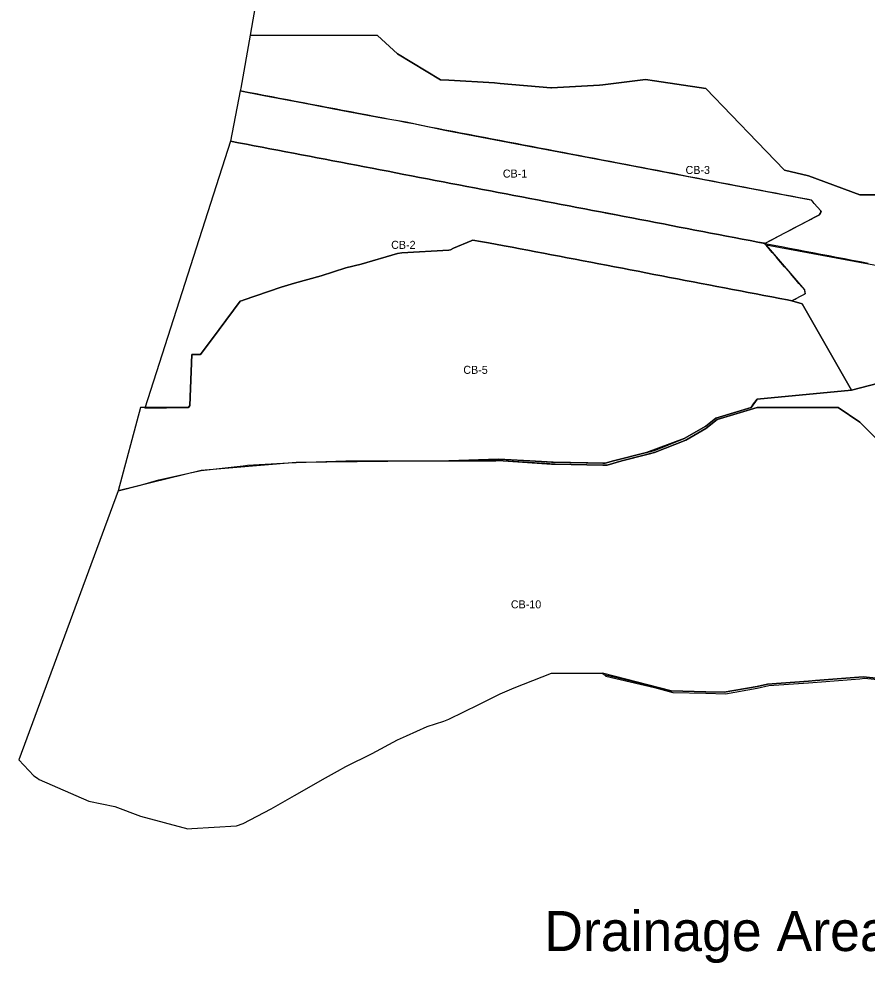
# Model space of a CAD drawing. Extents: x 2451 to 3960, y 2751 to 3762.
# Drawn here: x 2451 to 2980, y 2751 to 3341 of the extents above; entities that cross this region are included whole.
import ezdxf

# ---------------------------------------------------------------- set-up
doc = ezdxf.new("R2010")
doc.units = 0
doc.layers.add('SURVEY - DRAINAGE - Area Shapes', color=7, linetype='Continuous')
doc.layers.add('SURVEY - DRAINAGE - Area Shapes Text', color=7, linetype='Continuous')

msp = doc.modelspace()

# ---------------------------------------------------------------- linework, layer by layer
at = {"layer": 'SURVEY - DRAINAGE - Area Shapes'}
msp.add_line((2941.5, 3169.47), (2941.5, 3169.48), dxfattribs=at)
for points in [[(2670.29, 3761.98), (2595.31, 3330.82), (2674.6, 3330.56), (2687.08, 3319.1), (2713.92, 3302.79), (2719.15, 3302.62), (2747.77, 3300.95), (2751.23, 3300.64), (2782.84, 3297.86), (2783.31, 3297.89), (2813.27, 3299.56), (2815.38, 3299.78), (2842, 3303.03), (2847.46, 3302.35), (2879.54, 3297.37), (2911.62, 3264.19), (2928.65, 3246.56), (2943.69, 3242.98), (2975.77, 3231), (3007.85, 3231)], [(3007.85, 3231), (2975.77, 3231), (2943.69, 3242.98), (2928.65, 3246.56), (2911.62, 3264.19), (2879.54, 3297.37), (2847.46, 3302.35), (2842, 3303.03), (2815.38, 3299.78), (2813.27, 3299.56), (2783.31, 3297.89), (2782.84, 3297.86), (2751.23, 3300.64), (2747.77, 3300.95), (2719.15, 3302.62), (2713.92, 3302.79), (2687.08, 3319.1), (2674.6, 3330.56), (2655, 3330.56), (2622.92, 3330.56), (2595.31, 3330.82), (2589.39, 3297.7), (2589.06, 3295.97), (2603.8, 3293.15), (2628.35, 3288.46), (2652.91, 3283.76), (2677.46, 3279.06), (2692.62, 3276.59), (2716.75, 3271.54), (2765.86, 3262.14), (2829.7, 3249.93), (2893.54, 3237.71), (2945.12, 3227.91), (2951.27, 3221.06), (2951.47, 3220.52), (2950.51, 3218.66), (2916.37, 3200.75), (2926.81, 3198.76), (2931.72, 3197.82), (2936.63, 3196.88), (2941.54, 3195.94), (2946.46, 3195), (2951.37, 3194.06), (2956.28, 3193.12), (2961.19, 3192.18), (2966.1, 3191.24), (2971.01, 3190.3), (2975.92, 3189.36), (2980.83, 3188.42)], [(2946.56, 3226.54), (2946.33, 3226.81), (2945.51, 3227.76), (2945.52, 3227.81), (2942.65, 3228.31), (2937.74, 3229.25), (2932.83, 3230.19), (2927.92, 3231.13), (2923, 3232.07), (2918.09, 3233.01), (2913.18, 3233.95), (2908.27, 3234.89), (2903.36, 3235.83), (2898.45, 3236.77), (2893.54, 3237.71), (2888.63, 3238.65), (2883.72, 3239.59), (2878.81, 3240.53), (2873.9, 3241.47), (2868.99, 3242.41), (2864.07, 3243.35), (2859.16, 3244.29), (2854.25, 3245.23), (2849.34, 3246.17), (2844.43, 3247.11), (2839.52, 3248.05), (2834.61, 3248.99), (2829.7, 3249.93), (2824.79, 3250.86), (2819.88, 3251.8), (2814.97, 3252.74), (2810.05, 3253.68), (2805.14, 3254.62), (2800.23, 3255.56), (2795.32, 3256.5), (2790.41, 3257.44), (2785.5, 3258.38), (2780.59, 3259.32), (2775.68, 3260.26), (2770.77, 3261.2), (2765.86, 3262.14), (2760.95, 3263.08), (2756.03, 3264.02), (2751.12, 3264.96), (2746.21, 3265.9), (2741.3, 3266.84), (2736.39, 3267.78), (2731.48, 3268.72), (2726.57, 3269.66), (2721.66, 3270.6), (2716.75, 3271.54), (2711.84, 3272.48), (2706.93, 3273.42), (2702.01, 3274.36), (2697.1, 3275.3), (2692.19, 3276.24), (2687.28, 3277.18), (2682.37, 3278.12), (2677.46, 3279.06), (2672.55, 3280), (2667.64, 3280.94), (2662.73, 3281.88), (2657.82, 3282.82), (2652.91, 3283.76), (2648, 3284.7), (2643.08, 3285.64), (2638.17, 3286.58), (2633.26, 3287.52), (2628.35, 3288.46), (2623.44, 3289.4), (2618.53, 3290.33), (2613.62, 3291.27), (2608.71, 3292.21), (2603.8, 3293.15), (2598.89, 3294.09), (2593.98, 3295.03), (2589.06, 3295.97), (2583.05, 3264.54), (2587.96, 3263.6), (2592.87, 3262.66), (2597.78, 3261.72), (2602.69, 3260.79), (2607.6, 3259.84), (2612.52, 3258.91), (2617.43, 3257.97), (2622.34, 3257.03), (2627.25, 3256.09), (2632.16, 3255.15), (2637.07, 3254.21), (2641.98, 3253.27), (2646.89, 3252.33), (2651.8, 3251.39), (2656.71, 3250.45), (2661.62, 3249.51), (2666.54, 3248.57), (2671.45, 3247.63), (2676.36, 3246.69), (2681.27, 3245.75), (2686.18, 3244.81), (2691.09, 3243.87), (2696, 3242.93), (2700.91, 3241.99), (2705.82, 3241.05), (2710.73, 3240.11), (2715.64, 3239.17), (2720.55, 3238.23), (2725.47, 3237.29), (2730.38, 3236.35), (2735.29, 3235.41), (2740.2, 3234.47), (2745.11, 3233.53), (2750.02, 3232.59), (2754.93, 3231.65), (2759.84, 3230.71), (2764.75, 3229.77), (2769.66, 3228.83), (2774.57, 3227.89), (2779.49, 3226.95), (2784.4, 3226.01), (2789.31, 3225.07), (2794.22, 3224.13), (2799.13, 3223.19), (2804.04, 3222.25), (2808.95, 3221.32), (2813.86, 3220.37), (2818.77, 3219.44), (2823.68, 3218.5), (2828.59, 3217.56), (2833.51, 3216.62), (2838.42, 3215.68), (2843.33, 3214.74), (2848.24, 3213.8), (2853.15, 3212.86)], [(2941.5, 3169.48), (2941.5, 3169.51), (2941.29, 3171.55), (2937.68, 3175.76), (2935.89, 3177.84), (2933.52, 3180.6), (2932.33, 3181.99), (2929.36, 3185.45), (2928.73, 3186.18), (2925.19, 3190.3), (2923.44, 3192.34), (2921.03, 3195.14), (2917.21, 3199.58), (2916.87, 3199.99), (2916.69, 3200.19), (2916.17, 3200.8), (2912.08, 3201.58), (2907.17, 3202.52), (2902.26, 3203.46), (2897.35, 3204.4), (2892.44, 3205.34), (2887.53, 3206.28), (2882.61, 3207.22), (2877.7, 3208.16), (2872.79, 3209.1), (2867.88, 3210.04), (2862.97, 3210.98), (2858.06, 3211.92), (2853.15, 3212.86), (2848.24, 3213.8), (2843.33, 3214.74), (2838.42, 3215.68), (2833.51, 3216.62), (2828.59, 3217.56), (2823.68, 3218.5), (2813.86, 3220.37), (2808.95, 3221.32), (2804.04, 3222.25), (2799.13, 3223.19), (2794.22, 3224.13), (2789.31, 3225.07), (2784.4, 3226.01), (2779.49, 3226.95), (2774.57, 3227.89), (2769.66, 3228.83), (2764.75, 3229.77), (2759.84, 3230.71), (2754.93, 3231.65), (2750.02, 3232.59), (2745.11, 3233.53), (2740.2, 3234.47), (2735.29, 3235.41), (2730.38, 3236.35), (2725.47, 3237.29), (2720.55, 3238.23), (2715.64, 3239.17), (2710.73, 3240.11), (2705.82, 3241.05), (2700.91, 3241.99), (2696, 3242.93), (2691.09, 3243.87), (2686.18, 3244.81), (2681.27, 3245.75), (2676.36, 3246.69), (2671.45, 3247.63), (2666.54, 3248.57), (2661.62, 3249.51), (2656.71, 3250.45), (2651.8, 3251.39), (2646.89, 3252.33), (2641.98, 3253.27), (2637.07, 3254.21), (2632.16, 3255.15), (2627.25, 3256.09), (2622.34, 3257.03), (2617.43, 3257.97), (2612.52, 3258.91), (2607.6, 3259.84), (2602.69, 3260.79), (2597.78, 3261.72), (2592.87, 3262.66), (2587.96, 3263.6), (2583.05, 3264.54), (2529.52, 3097.95), (2556.79, 3098.25), (2557.54, 3099.53), (2558.77, 3131.44), (2564.24, 3131.44), (2575.84, 3146.96), (2589.08, 3164.62), (2590.36, 3165.13), (2590.85, 3165.3), (2614.5, 3173.34), (2622.92, 3175.82), (2639.57, 3180.59), (2655, 3185.44), (2664.6, 3187.88), (2687.08, 3194.37), (2689.86, 3194.93), (2719.15, 3196.61), (2720.19, 3196.74), (2722.15, 3197.81), (2733.09, 3202.35), (2733.51, 3202.53), (2734.13, 3202.78), (2739.06, 3201.9), (2743.98, 3201.01), (2753.83, 3199.28), (2758.74, 3198.34), (2763.65, 3197.4), (2768.56, 3196.46), (2773.47, 3195.52), (2778.38, 3194.58), (2783.29, 3193.64), (2788.2, 3192.7), (2793.11, 3191.76), (2798.03, 3190.83), (2802.94, 3189.89), (2807.85, 3188.95), (2812.76, 3188.01), (2817.67, 3187.07), (2822.58, 3186.13), (2827.49, 3185.19), (2832.4, 3184.25), (2837.31, 3183.31), (2842.22, 3182.37), (2847.13, 3181.43), (2852.05, 3180.49), (2856.96, 3179.55), (2861.87, 3178.61), (2866.78, 3177.67), (2871.69, 3176.73), (2876.6, 3175.79), (2881.51, 3174.85), (2886.42, 3173.91), (2891.33, 3172.97), (2896.24, 3172.03), (2901.15, 3171.09), (2906.07, 3170.15), (2910.98, 3169.21), (2915.89, 3168.27), (2920.8, 3167.33), (2925.71, 3166.39), (2930.62, 3165.45)], [(2951.47, 3220.52), (2951.38, 3220.75), (2951.27, 3221.06), (2947.25, 3225.75), (2946.56, 3226.54)], [(2933.91, 3209.96), (2934.06, 3210.04), (2934.37, 3210.2), (2939.72, 3213), (2942.41, 3214.41), (2945.38, 3215.97), (2946.66, 3216.64), (2950.51, 3218.66), (2950.59, 3218.81), (2951.26, 3220.11)], [(2951.26, 3220.11), (2951.45, 3220.47), (2951.47, 3220.51)], [(2951.47, 3220.51), (2951.47, 3220.52)], [(2853.15, 3212.86), (2858.06, 3211.92), (2862.97, 3210.98), (2867.88, 3210.04), (2872.79, 3209.1), (2877.7, 3208.16), (2882.61, 3207.22), (2887.53, 3206.28), (2892.44, 3205.34), (2897.35, 3204.4), (2902.26, 3203.46), (2907.17, 3202.52), (2912.08, 3201.58), (2916.36, 3200.76), (2917.09, 3201.14), (2921.16, 3203.27), (2922.74, 3204.1), (2925.41, 3205.5), (2928.4, 3207.07), (2929.66, 3207.73), (2933.44, 3209.71)], [(2933.44, 3209.71), (2933.91, 3209.96)], [(2970.53, 3109.1), (2939.7, 3163.1), (2933.29, 3164.94), (2930.62, 3165.45), (2925.71, 3166.39), (2920.8, 3167.33), (2915.89, 3168.27), (2910.98, 3169.21), (2906.07, 3170.15), (2901.15, 3171.09), (2896.24, 3172.03), (2891.33, 3172.97), (2886.42, 3173.91), (2881.51, 3174.85), (2876.6, 3175.79), (2871.69, 3176.73), (2866.78, 3177.67), (2861.87, 3178.61), (2856.96, 3179.55), (2852.05, 3180.49), (2847.13, 3181.43), (2842.22, 3182.37), (2837.31, 3183.31), (2832.4, 3184.25), (2827.49, 3185.19), (2822.58, 3186.13), (2817.67, 3187.07), (2812.76, 3188.01), (2807.85, 3188.95), (2802.94, 3189.89), (2798.03, 3190.83), (2793.11, 3191.76), (2788.2, 3192.7), (2783.29, 3193.64), (2778.38, 3194.58), (2773.47, 3195.52), (2768.56, 3196.46), (2763.65, 3197.4), (2758.74, 3198.34), (2753.83, 3199.28), (2743.98, 3201.01), (2739.06, 3201.9), (2734.13, 3202.78), (2733.51, 3202.53), (2733.09, 3202.35), (2722.15, 3197.81), (2720.19, 3196.74), (2719.15, 3196.61), (2689.86, 3194.93), (2687.08, 3194.37), (2664.6, 3187.88), (2655, 3185.44), (2639.57, 3180.59), (2622.92, 3175.82), (2614.5, 3173.34), (2590.85, 3165.3), (2590.36, 3165.13), (2589.08, 3164.62), (2575.84, 3146.96), (2564.24, 3131.44), (2558.77, 3131.44), (2557.54, 3099.53), (2556.79, 3098.25), (2526.69, 3098.25)], [(2930.62, 3165.45), (2933.29, 3164.94), (2933.81, 3165.21), (2934.71, 3165.69), (2935.33, 3166.01), (2935.87, 3166.29), (2938.33, 3167.58), (2941.12, 3169.04), (2941.14, 3169.07), (2941.5, 3169.47)], [(3004.26, 3117.78), (2970.53, 3109.1), (2911.62, 3103.57), (2907.93, 3098.25), (2885.88, 3091.69), (2879.54, 3086.59), (2866.14, 3078.92), (2842.57, 3070.12), (2821.93, 3065.06), (2816.85, 3063.54), (2784.29, 3064.05), (2769.66, 3065.06), (2750.27, 3066.05), (2719.15, 3065.06), (2748.64, 3065.06), (2751.14, 3065.16), (2751.23, 3065.15), (2753.05, 3065.06), (2783.31, 3063), (2785.49, 3062.81), (2815.38, 3062.35), (2818.05, 3062.31), (2827.25, 3065.06), (2843.59, 3069.07), (2847.46, 3070.18), (2867.08, 3077.95), (2879.54, 3085.08), (2886.71, 3090.83), (2911.62, 3098.25), (2943.69, 3098.25), (2962.11, 3098.25), (2975.77, 3089.06), (3000.01, 3065.06)], [(2526.69, 3098.25), (2512.77, 3046.27), (2526.69, 3049.77), (2538.31, 3053.05), (2558.77, 3057.64), (2564.75, 3058.87), (2590.85, 3061.96), (2593.57, 3062.24), (2622.92, 3063.91), (2623.98, 3063.97), (2655, 3065.06), (2687.08, 3065.06), (2719.15, 3065.06), (2724.92, 3065.06), (2750.27, 3066.05), (2751.23, 3066), (2769.66, 3065.06), (2783.31, 3064.13), (2784.29, 3064.05), (2815.38, 3063.56), (2816.85, 3063.54), (2821.93, 3065.06), (2842.57, 3070.12), (2847.46, 3071.52), (2866.14, 3078.92), (2879.54, 3086.59), (2885.88, 3091.69), (2907.93, 3098.25), (2909.29, 3100.66), (2911.62, 3103.57), (2970.53, 3109.1)], [(3000.01, 3065.06), (2975.77, 3089.06), (2962.11, 3098.25), (2911.62, 3098.25), (2886.71, 3090.83), (2879.54, 3085.08), (2867.08, 3077.95), (2847.46, 3070.18), (2827.25, 3065.06), (2818.05, 3062.31), (2815.38, 3062.35), (2785.49, 3062.81), (2753.05, 3065.06), (2719.15, 3065.06), (2623.98, 3063.97), (2564.75, 3058.87), (2512.77, 3046.27), (2450.9, 2878.35), (2460.31, 2868.25), (2462.54, 2866.95), (2463.5, 2865.94), (2494.62, 2852.56), (2510.8, 2849.19), (2526.69, 2843.02), (2556.3, 2835.3), (2558.77, 2835.41), (2586.71, 2837.03), (2590.85, 2838.49), (2608.41, 2847.76), (2622.92, 2856.03), (2629.12, 2859.53), (2640.4, 2865.94), (2649.83, 2871.29), (2655, 2874.17), (2671.29, 2882.27), (2687.08, 2890.69), (2692.76, 2893.24), (2705.69, 2899.12), (2715.99, 2902.4), (2719.15, 2903.64), (2737.92, 2912.89), (2751.23, 2919.5), (2760.08, 2923.16), (2783.31, 2932.31), (2815.12, 2932.31), (2815.38, 2932.17), (2816.17, 2931.5), (2847.46, 2924.11), (2858.02, 2921.38), (2879.54, 2920.8), (2890.97, 2920.48), (2911.62, 2924.18), (2918.09, 2925.62), (2943.69, 2927.44), (2948.1, 2927.75), (2948.1, 2927.75), (2977.86, 2930.15), (3007.85, 2926.96)], [(3013.64, 2926.32), (2977.86, 2930.15), (2977.86, 2930.15), (2948.1, 2927.75), (2948.1, 2927.75), (2943.69, 2927.44), (2918.09, 2925.62), (2911.62, 2924.18), (2890.97, 2920.48), (2879.54, 2920.8), (2858.02, 2921.38), (2815.12, 2932.31), (2815.38, 2932.17), (2817.1, 2930.54), (2847.46, 2923.37), (2858.98, 2920.39), (2879.54, 2919.84), (2891.93, 2919.49), (2911.62, 2923.01), (2919.01, 2924.66), (2943.69, 2926.41), (2949.03, 2926.79), (2975.77, 2928.92), (2978.78, 2929.2), (3007.85, 2926.11)]]:
    msp.add_lwpolyline(points, dxfattribs=at)
msp.add_lwpolyline([(2939.7, 3163.1), (2970.53, 3109.1), (3004.26, 3117.78), (3006.19, 3069.56), (3049.56, 3033.88), (3116.05, 3044.49), (3178.69, 3108.14), (3187.16, 3123.41), (3163.77, 3153.84), (2917.21, 3199.58), (2941.21, 3171.81), (2941.55, 3169.36), (2941.04, 3168.82), (2933.29, 3164.94)], close=True, dxfattribs=at)

# ---------------------------------------------------------------- texts
at = {"layer": 'SURVEY - DRAINAGE - Area Shapes Text'}
for s, height, p in [('CB-3', 5, (2866.94, 3244.1)), ('CB-1', 5, (2752.92, 3241.85)), ('CB-2', 5, (2683.22, 3197.34)), ('CB-5', 5, (2728.25, 3119.3)), ('CB-10', 5, (2757.93, 2972.88)), ('Drainage Areas for Storm Drainage System', 25, (2778.76, 2758.91))]:
    msp.add_text(s, height=height, dxfattribs=at).set_placement(p)

doc.saveas('drawing.dxf')
